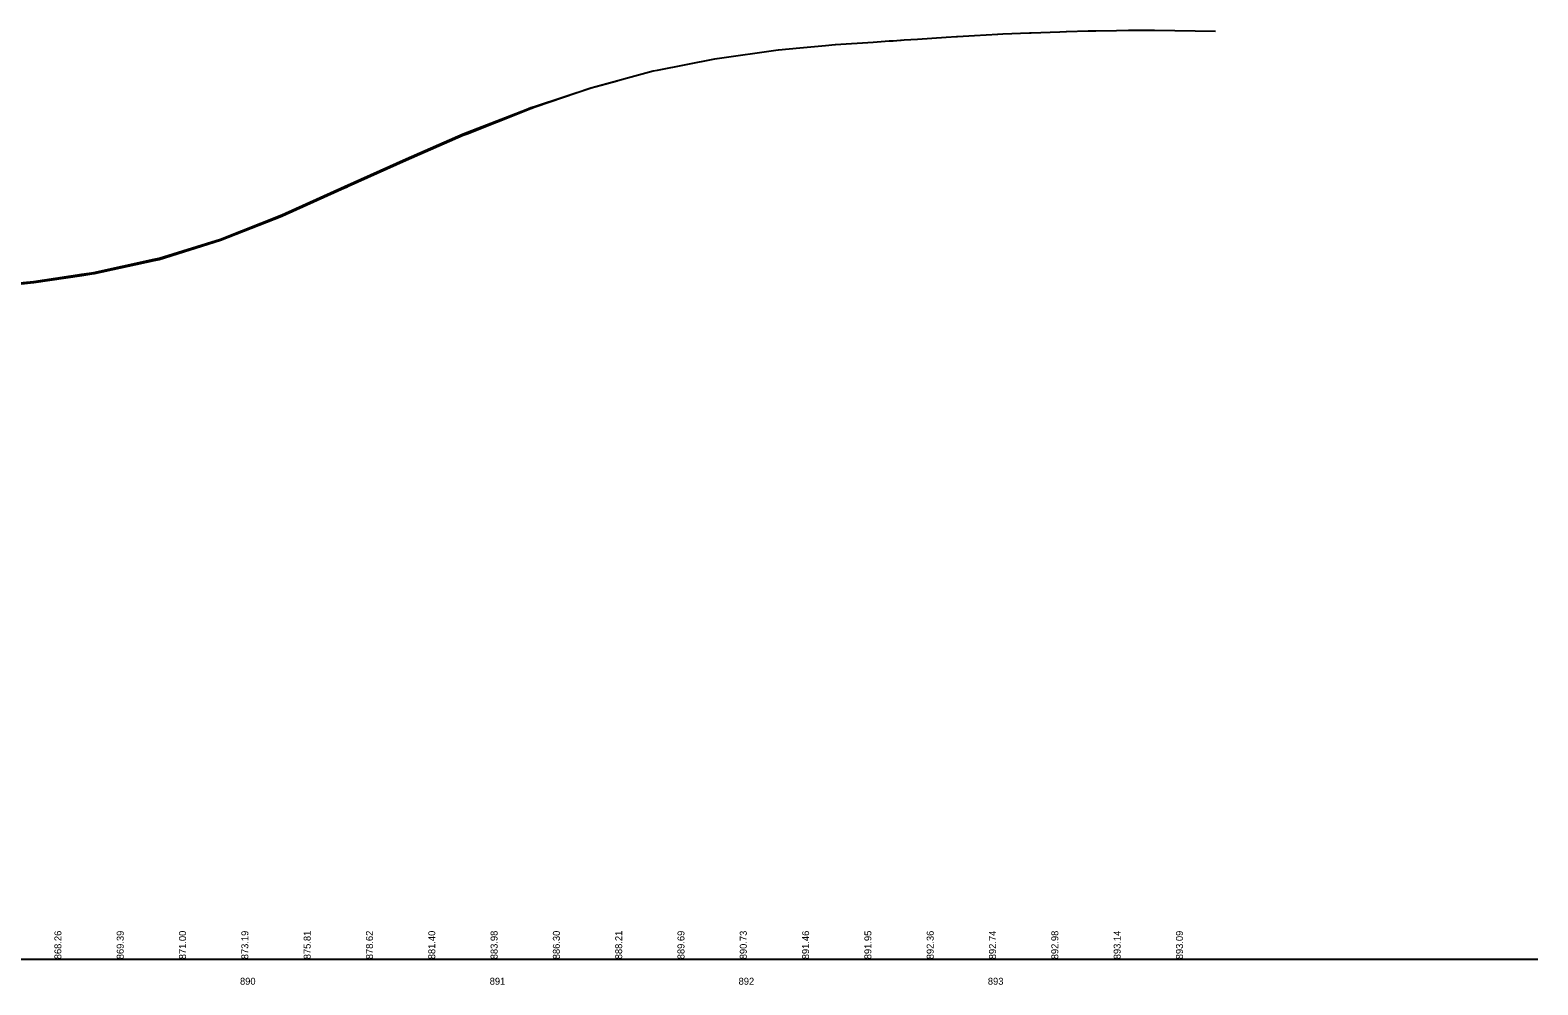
# Model space of a CAD drawing. Extents: x 223098 to 226975, y 386666 to 387582.
# Drawn here: x 226370 to 226975, y 387072 to 387455 of the extents above; entities that cross this region are included whole.
import ezdxf

# ---------------------------------------------------------------- set-up
doc = ezdxf.new("R2010")
doc.units = 0
for name, color, linetype in [('GE_P_Alignment_100_Bearings', 7, 'Continuous'), ('GE_P_Alignment_100_Distances', 7, 'Continuous'), ('GE_P_Alignment_100_Stations', 7, 'Continuous'), ('RD_X_Fence', 7, 'Continuous')]:
    doc.layers.add(name, color=color, linetype=linetype)

msp = doc.modelspace()

# ---------------------------------------------------------------- linework, layer by layer
at = {"layer": 'GE_P_Alignment_100_Bearings'}
msp.add_lwpolyline([(226361.98, 387352.33), (226371.76, 387353.36), (226371.95, 387353.38), (226391.12, 387356.27), (226395.93, 387356.98), (226396.28, 387357.05), (226420.26, 387362.2), (226422.21, 387362.62), (226446.78, 387370.35), (226446.86, 387370.38), (226471.4, 387380.02), (226471.75, 387380.15), (226496.6, 387391.37), (226497.34, 387391.69), (226498.07, 387392.01), (226521.29, 387402.51), (226544.22, 387412.47), (226545.77, 387413.09), (226569.38, 387422.45), (226571.27, 387423.2), (226573.13, 387423.84), (226595.42, 387431.41), (226597.37, 387431.96), (226620.44, 387438.26), (226622.11, 387438.61), (226645.18, 387443.15), (226646.09, 387443.29), (226670.62, 387446.69), (226670.69, 387446.7), (226679.32, 387447.5), (226689.63, 387448.45), (226693.46, 387448.79), (226693.62, 387448.8), (226708.69, 387449.84), (226715.15, 387450.27), (226716.65, 387450.37), (226719.72, 387450.55), (226719.86, 387450.56), (226719.96, 387450.57), (226721.15, 387450.67), (226726.54, 387451.02), (226737.94, 387451.76), (226742.09, 387452.03), (226742.2, 387452.03), (226742.44, 387452.05), (226742.56, 387452.06), (226749.34, 387452.47), (226758.72, 387453.01), (226758.75, 387453.02), (226760.74, 387453.11), (226771.44, 387453.57), (226771.6, 387453.57), (226771.77, 387453.57), (226772.14, 387453.59), (226783.54, 387453.94), (226786.18, 387454.01), (226786.23, 387454.01), (226794.93, 387454.29), (226798.01, 387454.38), (226798.02, 387454.38), (226806.33, 387454.53), (226811.15, 387454.6), (226811.19, 387454.6), (226817.73, 387454.57), (226821.54, 387454.55), (226846.09, 387454.16)], dxfattribs=at)
at = {"layer": 'GE_P_Alignment_100_Distances'}
msp.add_line((225757.98, 387082), (226975.39, 387082), dxfattribs=at)
at = {"layer": 'GE_P_Alignment_100_Stations'}
for points in [[(226553.48, 387416.64), (226569.43, 387422.81), (226571.33, 387423.54), (226573.2, 387424.16), (226595.55, 387431.54), (226597.5, 387432.07), (226605.98, 387434.31)], [(226357.98, 387352.4), (226361.98, 387352.83), (226371.76, 387353.86), (226391.12, 387356.77), (226395.93, 387357.48), (226420.26, 387362.7), (226422.21, 387363.12), (226446.78, 387370.85), (226471.4, 387380.52), (226496.6, 387391.87), (226521.29, 387403.01), (226544.22, 387412.97), (226553.48, 387416.64)]]:
    msp.add_lwpolyline(points, dxfattribs=at)

# ---------------------------------------------------------------- texts
at = {"layer": 'RD_X_Fence'}
for s, p in [('868.26', (226382.98, 387082)), ('869.39', (226407.98, 387082)), ('871.00', (226432.98, 387082)), ('873.19', (226457.98, 387082)), ('875.81', (226482.98, 387082)), ('878.62', (226507.98, 387082)), ('881.40', (226532.98, 387082)), ('883.98', (226557.98, 387082)), ('886.30', (226582.98, 387082)), ('888.21', (226607.98, 387082)), ('889.69', (226632.98, 387082)), ('890.73', (226657.98, 387082)), ('891.46', (226682.98, 387082)), ('891.95', (226707.98, 387082)), ('892.36', (226732.98, 387082)), ('892.74', (226757.98, 387082)), ('892.98', (226782.98, 387082)), ('893.14', (226807.98, 387082)), ('893.09', (226832.98, 387082))]:
    msp.add_text(s, height=2.8, rotation=90, dxfattribs=at).set_placement(p)
for s, p in [('890', (226454.64, 387071.78)), ('891', (226554.83, 387071.78)), ('892', (226654.7, 387071.78)), ('893', (226754.71, 387071.78))]:
    msp.add_text(s, height=2.8, dxfattribs=at).set_placement(p)

doc.saveas('drawing.dxf')
